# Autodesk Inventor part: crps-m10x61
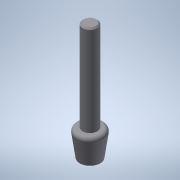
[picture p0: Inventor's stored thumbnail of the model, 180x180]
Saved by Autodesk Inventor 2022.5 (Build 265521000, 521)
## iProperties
Created: 2016-12
Part Number: crps-m10x61
Material: 一般
Document SubType Name: Modeling
Designer: imaocorp
Density: 1 g/cm^3
Appearance: 既定
Author: imaocorp
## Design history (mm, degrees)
node "crps-m10x61.x_t1"
node "crps-m10x61"
node "Base1"
